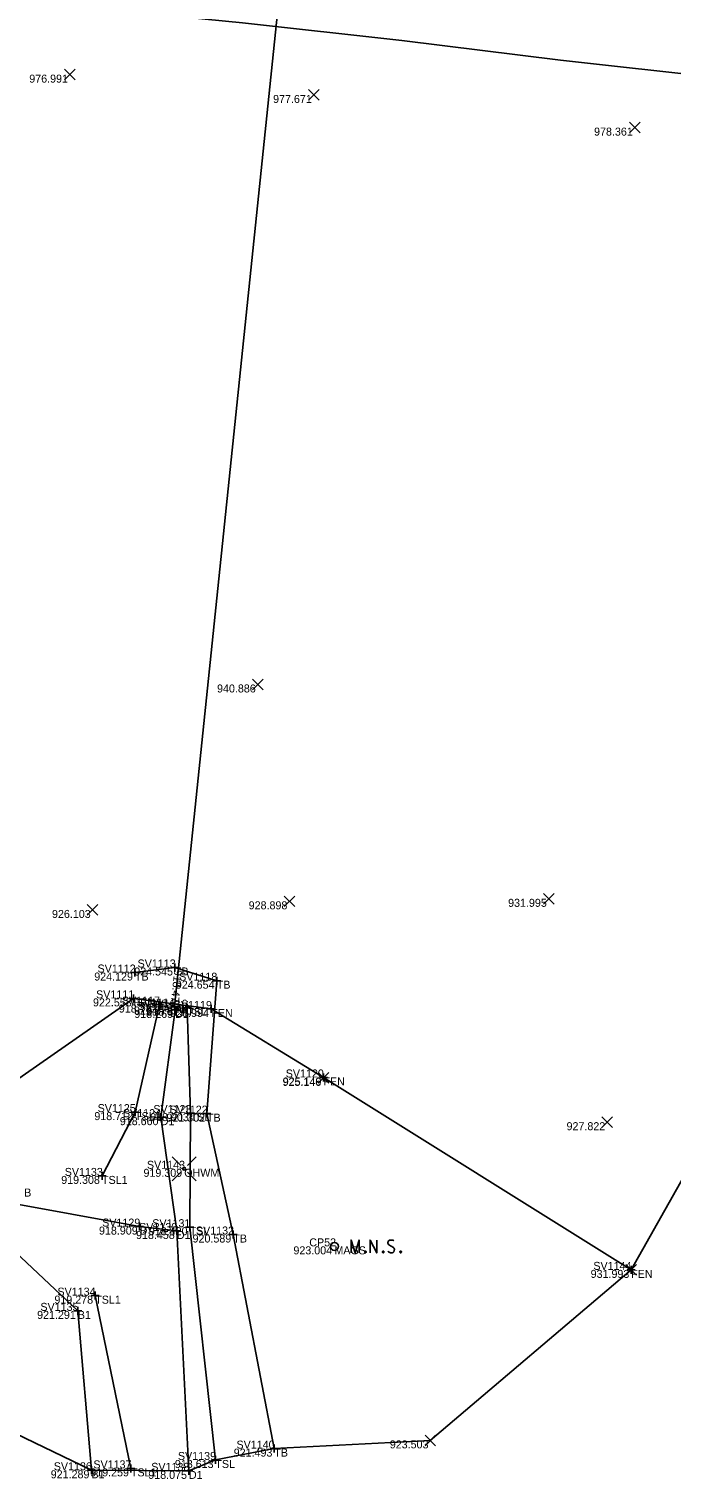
# Model space of a CAD drawing. Extents: x 2065431 to 2068157, y 709104 to 709719.
# Drawn here: x 2067254.1 to 2067334.4, y 709103.8 to 709285 of the extents above; entities that cross this region are included whole.
import ezdxf

# ---------------------------------------------------------------- set-up
doc = ezdxf.new("R2010")
doc.units = 0
for name, color, linetype in [('_CIVIL_CONSTRUCTION', 7, 'Continuous'), ('DR_X_Storm_Sewer', 7, 'Continuous'), ('DT_X_Break_Line', 7, 'Continuous'), ('DT_X_Terrain_Boundary', 7, 'Continuous'), ('RD_X_Fence', 7, 'Continuous'), ('RS_Raster1', 7, 'Continuous'), ('RW_X_CL_100_Bearings', 7, 'Continuous'), ('RW_X_CL_100_Curve_Data', 7, 'Continuous'), ('RW_X_CL_100_Stations', 7, 'Continuous'), ('RW_X_Fee_WL', 7, 'Continuous'), ('SC_Scratch1', 7, 'Continuous'), ('SV_X_Break_Lines', 7, 'Continuous'), ('SV_X_Mon_Cells_Found', 7, 'Continuous'), ('SV_X_Text_Elevation', 7, 'Continuous'), ('SV_X_Text_Name', 7, 'Continuous'), ('SV_X_Toe_of_Slope', 7, 'Continuous'), ('SV_X_Top_of_Bank', 7, 'Continuous')]:
    doc.layers.add(name, color=color, linetype=linetype)

msp = doc.modelspace()

# ---------------------------------------------------------------- linework, layer by layer
at = {"layer": '_CIVIL_CONSTRUCTION'}
for p, q in [((2067272.26, 709163.37), (2067272.26, 709162.37)), ((2067271.76, 709162.87), (2067272.76, 709162.87)), ((2067272.26, 709162.87), (2067272.26, 709162.87))]:
    msp.add_line(p, q, dxfattribs=at)
at = {"layer": 'DR_X_Storm_Sewer'}
msp.add_line((2067313.91, 709564.11), (2067272.26, 709162.87), dxfattribs=at)
at = {"layer": 'DT_X_Break_Line'}
msp.add_lwpolyline([(2067101.73, 709304.2), (2067121.64, 709302.33), (2067141.54, 709300.39), (2067161.43, 709298.3), (2067181.3, 709296.03), (2067201.15, 709293.56), (2067221.05, 709291.6), (2067240.96, 709289.7), (2067260.87, 709287.74), (2067280.77, 709285.77), (2067300.65, 709283.57), (2067320.49, 709281.09), (2067340.37, 709278.88), (2067360.28, 709276.99), (2067380.18, 709275.07), (2067400.09, 709273.09), (2067419.99, 709271.15), (2067439.91, 709269.35), (2067459.83, 709267.56), (2067469.03, 709266.73)], dxfattribs=at)
at = {"layer": 'DT_X_Terrain_Boundary'}
msp.add_lwpolyline([(2067102.37, 709178.61), (2067140.67, 709165.08), (2067183.02, 709149.8), (2067239.23, 709115.87), (2067261.89, 709104.93), (2067274.06, 709104.86), (2067277.37, 709106.22), (2067284.73, 709107.64), (2067304.22, 709108.67), (2067329.31, 709129.97), (2067346.3, 709160.09), (2067342.01, 709185.45), (2067370.56, 709268.21), (2067411.97, 709264.45), (2067464.57, 709259.36), (2067538.62, 709266.34)], dxfattribs=at)
at = {"layer": 'RD_X_Fence'}
for p, q in [((2067226.35, 709135.4), (2067267.15, 709163.89)), ((2067290.87, 709154.01), (2067329.31, 709129.97))]:
    msp.add_line(p, q, dxfattribs=at)
msp.add_lwpolyline([(2067290.87, 709154.01), (2067276.86, 709162.57), (2067267.15, 709163.89)], dxfattribs=at)
at = {"layer": 'RS_Raster1'}
for p, q in [((2067266.82, 709167.12), (2067267.82, 709167.12)), ((2067267.32, 709167.62), (2067267.32, 709166.62)), ((2067267.32, 709167.12), (2067267.32, 709167.12)), ((2067271.81, 709167.75), (2067272.81, 709167.75)), ((2067272.31, 709168.25), (2067272.31, 709167.25)), ((2067272.31, 709167.75), (2067272.31, 709167.75)), ((2067277.05, 709166.1), (2067278.05, 709166.1)), ((2067277.55, 709166.6), (2067277.55, 709165.6)), ((2067277.55, 709166.1), (2067277.55, 709166.1)), ((2067266.65, 709163.89), (2067267.65, 709163.89)), ((2067267.15, 709164.39), (2067267.15, 709163.39)), ((2067267.15, 709163.89), (2067267.15, 709163.89)), ((2067269.88, 709163.12), (2067270.88, 709163.12)), ((2067270.38, 709163.62), (2067270.38, 709162.62)), ((2067270.38, 709163.12), (2067270.38, 709163.12)), ((2067273.85, 709163.23), (2067273.85, 709162.23)), ((2067271.83, 709162.45), (2067272.83, 709162.45)), ((2067272.33, 709162.95), (2067272.33, 709161.95)), ((2067272.33, 709162.45), (2067272.33, 709162.45)), ((2067273.35, 709162.73), (2067274.35, 709162.73)), ((2067273.85, 709162.73), (2067273.85, 709162.73)), ((2067276.36, 709162.57), (2067277.36, 709162.57)), ((2067276.86, 709163.07), (2067276.86, 709162.07)), ((2067276.86, 709162.57), (2067276.86, 709162.57)), ((2067290.87, 709154.51), (2067290.87, 709153.51)), ((2067290.37, 709154.01), (2067291.37, 709154.01)), ((2067290.87, 709154.01), (2067290.87, 709154.01)), ((2067266.83, 709149.68), (2067267.83, 709149.68)), ((2067267.33, 709150.18), (2067267.33, 709149.18)), ((2067267.33, 709149.68), (2067267.33, 709149.68)), ((2067270.04, 709149.05), (2067271.04, 709149.05)), ((2067270.54, 709149.55), (2067270.54, 709148.55)), ((2067270.54, 709149.05), (2067270.54, 709149.05)), ((2067273.78, 709149.56), (2067274.78, 709149.56)), ((2067274.28, 709150.06), (2067274.28, 709149.06)), ((2067274.28, 709149.56), (2067274.28, 709149.56)), ((2067275.82, 709149.49), (2067276.82, 709149.49)), ((2067276.32, 709149.99), (2067276.32, 709148.99)), ((2067276.32, 709149.49), (2067276.32, 709149.49)), ((2067262.71, 709141.71), (2067263.71, 709141.71)), ((2067263.21, 709142.21), (2067263.21, 709141.21)), ((2067263.21, 709141.71), (2067263.21, 709141.71)), ((2067267.41, 709135.38), (2067268.41, 709135.38)), ((2067267.91, 709135.88), (2067267.91, 709134.88)), ((2067267.91, 709135.38), (2067267.91, 709135.38)), ((2067272.06, 709134.83), (2067273.06, 709134.83)), ((2067272.56, 709135.33), (2067272.56, 709134.33)), ((2067272.56, 709134.83), (2067272.56, 709134.83)), ((2067273.67, 709135.3), (2067274.67, 709135.3)), ((2067274.17, 709135.8), (2067274.17, 709134.8)), ((2067274.17, 709135.3), (2067274.17, 709135.3)), ((2067279.11, 709134.39), (2067280.11, 709134.39)), ((2067279.61, 709134.89), (2067279.61, 709133.89)), ((2067279.61, 709134.39), (2067279.61, 709134.39)), ((2067329.31, 709130.47), (2067329.31, 709129.47)), ((2067328.81, 709129.97), (2067329.81, 709129.97)), ((2067329.31, 709129.97), (2067329.31, 709129.97)), ((2067262.36, 709127.25), (2067262.36, 709126.25)), ((2067260.18, 709125.35), (2067260.18, 709124.35)), ((2067261.86, 709126.75), (2067262.86, 709126.75)), ((2067262.36, 709126.75), (2067262.36, 709126.75)), ((2067259.68, 709124.85), (2067260.68, 709124.85)), ((2067260.18, 709124.85), (2067260.18, 709124.85)), ((2067284.23, 709107.64), (2067285.23, 709107.64)), ((2067284.73, 709108.14), (2067284.73, 709107.14)), ((2067284.73, 709107.64), (2067284.73, 709107.64)), ((2067261.89, 709105.43), (2067261.89, 709104.43)), ((2067266.32, 709105.17), (2067267.32, 709105.17)), ((2067266.82, 709105.67), (2067266.82, 709104.67)), ((2067266.82, 709105.17), (2067266.82, 709105.17)), ((2067274.06, 709105.36), (2067274.06, 709104.36)), ((2067276.87, 709106.22), (2067277.87, 709106.22)), ((2067277.37, 709106.72), (2067277.37, 709105.72)), ((2067277.37, 709106.22), (2067277.37, 709106.22)), ((2067261.39, 709104.93), (2067262.39, 709104.93)), ((2067261.89, 709104.93), (2067261.89, 709104.93)), ((2067273.56, 709104.86), (2067274.56, 709104.86)), ((2067274.06, 709104.86), (2067274.06, 709104.86))]:
    msp.add_line(p, q, dxfattribs=at)
at = {"layer": 'RW_X_CL_100_Bearings'}
for p, q in [((2067258.53, 709278.64), (2067259.87, 709279.97)), ((2067258.53, 709279.97), (2067259.87, 709278.64)), ((2067288.99, 709276.09), (2067290.33, 709277.43)), ((2067288.99, 709277.43), (2067290.33, 709276.09)), ((2067329.09, 709272.01), (2067330.43, 709273.35)), ((2067329.09, 709273.35), (2067330.43, 709272.01)), ((2067282.02, 709202.44), (2067283.35, 709203.78)), ((2067282.02, 709203.78), (2067283.35, 709202.44)), ((2067285.96, 709175.35), (2067287.3, 709176.68)), ((2067285.96, 709176.68), (2067287.3, 709175.35)), ((2067318.35, 709175.66), (2067319.68, 709177)), ((2067318.35, 709177), (2067319.68, 709175.66)), ((2067261.35, 709174.27), (2067262.69, 709175.61)), ((2067261.35, 709175.61), (2067262.69, 709174.27)), ((2067290.2, 709153.3), (2067291.53, 709154.63)), ((2067290.2, 709154.63), (2067291.53, 709153.3)), ((2067325.65, 709147.75), (2067326.98, 709149.09)), ((2067325.65, 709149.09), (2067326.98, 709147.75)), ((2067328.65, 709129.31), (2067329.98, 709130.64)), ((2067328.65, 709130.64), (2067329.98, 709129.31)), ((2067303.56, 709108), (2067304.89, 709109.34)), ((2067303.56, 709109.34), (2067304.89, 709108))]:
    msp.add_line(p, q, dxfattribs=at)
at = {"layer": 'RW_X_CL_100_Curve_Data'}
for points in [[(2067294.33, 709132.1), (2067294.33, 709133.7), (2067294.84, 709132.1), (2067295.32, 709133.7), (2067295.32, 709132.1)], [(2067296.09, 709132.32), (2067296.15, 709132.32), (2067296.18, 709132.29), (2067296.21, 709132.24), (2067296.21, 709132.18), (2067296.18, 709132.13), (2067296.15, 709132.1), (2067296.09, 709132.1), (2067296.06, 709132.13), (2067296.03, 709132.18), (2067296.03, 709132.24), (2067296.06, 709132.29), (2067296.09, 709132.32)], [(2067296.7, 709132.1), (2067296.7, 709133.7), (2067297.53, 709132.1), (2067297.53, 709133.7)], [(2067298.31, 709132.32), (2067298.36, 709132.32), (2067298.4, 709132.29), (2067298.43, 709132.24), (2067298.43, 709132.18), (2067298.4, 709132.13), (2067298.36, 709132.1), (2067298.31, 709132.1), (2067298.27, 709132.13), (2067298.24, 709132.18), (2067298.24, 709132.24), (2067298.27, 709132.29), (2067298.31, 709132.32)], [(2067299.67, 709133.59), (2067299.65, 709133.62), (2067299.62, 709133.64), (2067299.52, 709133.68), (2067299.4, 709133.7), (2067299.31, 709133.7), (2067299.28, 709133.7), (2067299.13, 709133.67), (2067299.01, 709133.59), (2067298.94, 709133.49), (2067298.91, 709133.39), (2067298.91, 709133.31), (2067298.94, 709133.21), (2067299.02, 709133.12), (2067299.63, 709132.75), (2067299.69, 709132.7), (2067299.71, 709132.65), (2067299.73, 709132.57), (2067299.73, 709132.5), (2067299.72, 709132.42), (2067299.71, 709132.37), (2067299.69, 709132.31), (2067299.66, 709132.26), (2067299.64, 709132.22), (2067299.61, 709132.18), (2067299.58, 709132.15), (2067299.53, 709132.13), (2067299.5, 709132.12), (2067299.4, 709132.1), (2067299.24, 709132.1), (2067299.15, 709132.13), (2067299, 709132.22), (2067298.91, 709132.29)], [(2067300.49, 709132.32), (2067300.55, 709132.32), (2067300.58, 709132.29), (2067300.61, 709132.24), (2067300.61, 709132.18), (2067300.58, 709132.13), (2067300.55, 709132.1), (2067300.49, 709132.1), (2067300.46, 709132.13), (2067300.42, 709132.18), (2067300.42, 709132.24), (2067300.46, 709132.29), (2067300.49, 709132.32)]]:
    msp.add_lwpolyline(points, dxfattribs=at)
msp.add_circle((2067292.24, 709132.9), 0.497, dxfattribs=at)
at = {"layer": 'RW_X_CL_100_Stations'}
for p, q in [((2067271.97, 709144.11), (2067273.06, 709143.02)), ((2067273.89, 709143.02), (2067274.99, 709144.11)), ((2067271.97, 709141.09), (2067273.06, 709142.18)), ((2067273.89, 709142.18), (2067274.99, 709141.09))]:
    msp.add_line(p, q, dxfattribs=at)
msp.add_circle((2067273.48, 709142.6), 0.17, dxfattribs=at)
at = {"layer": 'RW_X_Fee_WL'}
for points in [[(2067212.35, 709169.5), (2067227.66, 709161.36), (2067236.94, 709157.86), (2067242.62, 709150.21), (2067243.54, 709147.76), (2067250.98, 709138.46), (2067267.91, 709135.38), (2067272.56, 709134.83)], [(2067272.33, 709162.45), (2067270.54, 709149.05), (2067272.56, 709134.83), (2067274.06, 709104.86)]]:
    msp.add_lwpolyline(points, dxfattribs=at)
at = {"layer": 'SV_X_Break_Lines'}
msp.add_lwpolyline([(2067211.97, 709167.47), (2067226.2, 709159.23), (2067236.45, 709155.85), (2067241.36, 709145.7), (2067252.34, 709132.21), (2067260.18, 709124.85), (2067261.89, 709104.93)], dxfattribs=at)
at = {"layer": 'SV_X_Toe_of_Slope'}
for points in [[(2067270.38, 709163.12), (2067267.33, 709149.68), (2067263.21, 709141.71)], [(2067273.85, 709162.73), (2067274.28, 709149.56), (2067274.17, 709135.3), (2067277.37, 709106.22)], [(2067262.36, 709126.75), (2067266.82, 709105.17)]]:
    msp.add_lwpolyline(points, dxfattribs=at)
at = {"layer": 'SV_X_Top_of_Bank'}
msp.add_lwpolyline([(2067267.32, 709167.12), (2067272.31, 709167.75), (2067277.55, 709166.1), (2067276.32, 709149.49), (2067279.61, 709134.39), (2067284.73, 709107.64)], dxfattribs=at)

# ---------------------------------------------------------------- texts
at = {"layer": 'SC_Scratch1'}
msp.add_text("918.47'", height=1, rotation=264.0747, dxfattribs=at).set_placement((2067272.24, 709167.5))
at = {"layer": 'SV_X_Mon_Cells_Found'}
for s, p in [('SV1113', (2067267.65, 709167.75)), ('SV1112', (2067262.65, 709167.12)), ('SV1118', (2067272.85, 709166.1)), ('SV1111', (2067262.47, 709163.89)), ('SV1117', (2067265.69, 709163.12)), ('SV1114', (2067267.54, 709162.87)), ('SV1115', (2067267.66, 709162.45)), ('SV1116', (2067269.14, 709162.73)), ('SV1119', (2067272.18, 709162.57)), ('SV1120', (2067286.16, 709154.01)), ('SV1125', (2067262.66, 709149.68)), ('SV1123', (2067269.62, 709149.56)), ('SV1122', (2067271.65, 709149.49)), ('SV1124', (2067265.82, 709149.05)), ('SV1143', (2067268.82, 709142.6)), ('SV1133', (2067258.55, 709141.71)), ('SV1129', (2067263.23, 709135.38)), ('SV1131', (2067269.49, 709135.3)), ('SV1130', (2067267.85, 709134.83)), ('SV1132', (2067274.94, 709134.39)), ('CP52', (2067289.1, 709132.91)), ('SV1144', (2067324.59, 709129.97)), ('SV1134', (2067257.64, 709126.75)), ('SV1135', (2067255.51, 709124.85)), ('SV1139', (2067272.69, 709106.22)), ('SV1140', (2067280.01, 709107.64)), ('SV1136', (2067257.18, 709104.93)), ('SV1137', (2067262.13, 709105.17)), ('SV1138', (2067269.36, 709104.86))]:
    msp.add_text(s, height=1, dxfattribs=at).set_placement(p)
at = {"layer": 'SV_X_Text_Elevation'}
for s, p in [('TB', (2067267.32, 709166.12)), ('TB', (2067272.31, 709166.75)), ('TB', (2067277.55, 709165.1)), ('FEN', (2067267.15, 709162.89)), ('TSL1', (2067270.38, 709162.12)), ('PIO', (2067272.26, 709161.87)), ('D1', (2067272.33, 709161.45)), ('TSL', (2067273.85, 709161.73)), ('FEN', (2067276.86, 709161.57)), ('FEN', (2067290.87, 709153.01)), ('TSL1', (2067267.33, 709148.68)), ('D1', (2067270.54, 709148.05)), ('TSL', (2067274.28, 709148.56)), ('TB', (2067276.32, 709148.49)), ('TSL1', (2067263.21, 709140.71)), ('OHWM', (2067273.48, 709141.6)), ('B', (2067253.49, 709139.13)), ('D', (2067267.91, 709134.38)), ('D1', (2067272.56, 709133.83)), ('TSL', (2067274.17, 709134.3)), ('TB', (2067279.61, 709133.39)), ('MAGS', (2067292.24, 709131.91)), ('FEN', (2067329.31, 709128.97)), ('TSL1', (2067262.36, 709125.75)), ('B1', (2067260.18, 709123.85)), ('TB', (2067284.73, 709106.64)), ('TSL1', (2067266.82, 709104.17)), ('TSL', (2067277.37, 709105.22)), ('B1', (2067261.89, 709103.93)), ('D1', (2067274.06, 709103.86))]:
    msp.add_text(s, height=1, dxfattribs=at).set_placement(p)
at = {"layer": 'SV_X_Text_Name'}
for s, p in [('976.991', (2067254.12, 709278.3)), ('977.671', (2067284.58, 709275.76)), ('978.361', (2067324.68, 709271.68)), ('940.886', (2067277.58, 709202.11)), ('928.898', (2067281.53, 709175.02)), ('931.995', (2067313.94, 709175.33)), ('926.103', (2067256.96, 709173.94)), ('924.129', (2067262.24, 709166.12)), ('924.545', (2067267.24, 709166.75)), ('924.654', (2067272.43, 709165.1)), ('922.553', (2067262.08, 709162.89)), ('918.782', (2067265.31, 709162.12)), ('922.973', (2067267.2, 709161.87)), ('918.269', (2067267.25, 709161.45)), ('918.579', (2067268.76, 709161.73)), ('926.994', (2067271.73, 709161.57)), ('925.149', (2067285.79, 709153.01)), ('925.146', (2067285.76, 709152.96)), ('918.712', (2067262.25, 709148.68)), ('918.660', (2067265.43, 709148.05)), ('918.903', (2067269.22, 709148.56)), ('921.302', (2067271.25, 709148.49)), ('927.822', (2067321.24, 709147.42)), ('919.308', (2067258.11, 709140.71)), ('919.309', (2067268.39, 709141.6)), ('918.909', (2067262.83, 709134.38)), ('918.458', (2067267.46, 709133.83)), ('918.420', (2067269.06, 709134.3)), ('920.589', (2067274.52, 709133.39)), ('923.004', (2067287.12, 709131.91)), ('931.993', (2067324.25, 709128.97)), ('931.993', (2067324.25, 709128.97)), ('919.278', (2067257.26, 709125.75)), ('921.291', (2067255.1, 709123.85)), ('921.493', (2067279.66, 709106.64)), ('923.503', (2067299.16, 709107.67)), ('919.259', (2067261.74, 709104.17)), ('918.613', (2067272.31, 709105.22)), ('921.289', (2067256.8, 709103.93)), ('918.075', (2067268.99, 709103.86))]:
    msp.add_text(s, height=1, dxfattribs=at).set_placement(p)

doc.saveas('drawing.dxf')
